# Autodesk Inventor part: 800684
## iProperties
Created: 2007-10
Part Number: 800684
Document SubType Name: Modeling
Designer: AL
Density: 8.08 g/cm^3
Mass: 6.97935 g
Surface Area: 6.33239 cm^2
Volume: 0.86378 cm^3
Material: Stainless Steel
Description: PIVOT PIN
Component Category: Fasteners
Author: AL
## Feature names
1. Revolution1
